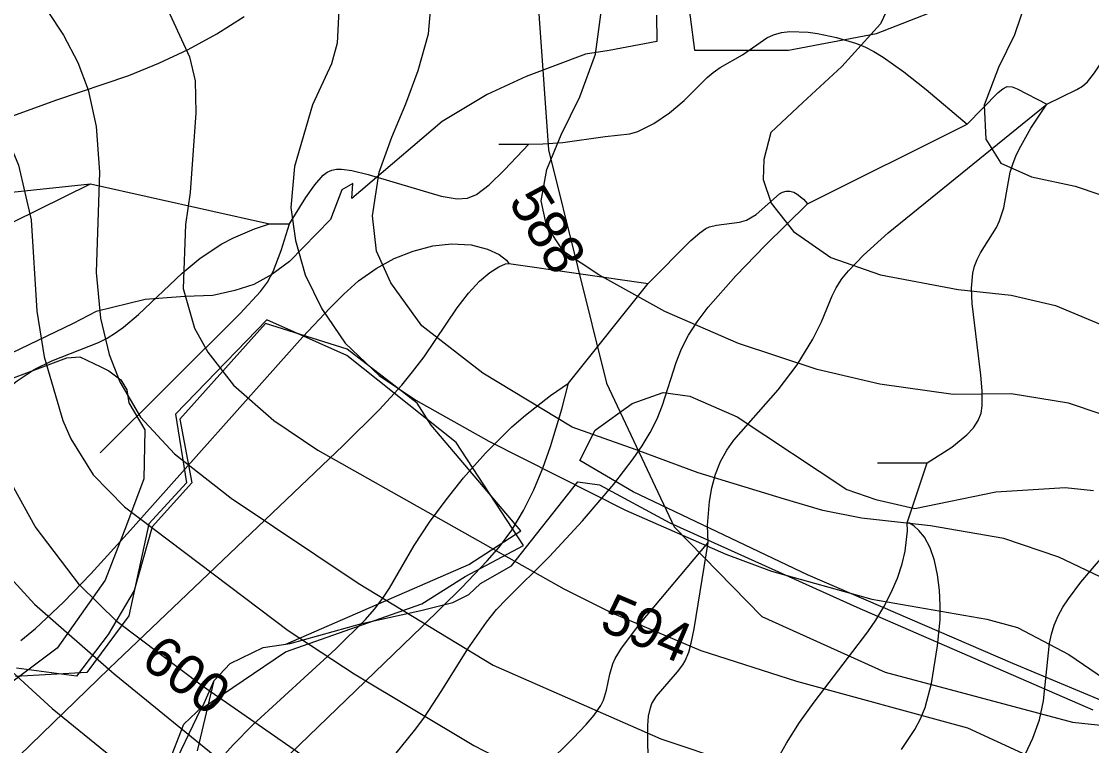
# Model space of a CAD drawing. Extents: x -709584 to -702006, y -1161789 to -1157496.
# Drawn here: x -706204.3 to -705935.7, y -1159597.9 to -1159416.2 of the extents above; entities that cross this region are included whole.
import ezdxf

# ---------------------------------------------------------------- set-up
doc = ezdxf.new("R2010")
doc.units = 0
for name, color, linetype in [('102_obvod PÚ', 7, 'Continuous'), ('120_vrstevnice hlavní', 7, 'Continuous'), ('121_vrstevnice hlavní_popis', 7, 'Continuous'), ('122_vrstevnice základní', 7, 'Continuous'), ('408_BPEJ_linie', 7, 'Continuous'), ('411_akumulovaný odtok', 7, 'Continuous'), ('419_LPIS PB', 7, 'Continuous')]:
    doc.layers.add(name, color=color, linetype=linetype)

msp = doc.modelspace()

# ---------------------------------------------------------------- linework, layer by layer
at = {"layer": '102_obvod PÚ'}
for points in [[(-706037.57, -1159406.69), (-706035.36, -1159423.47), (-706011.83, -1159423.45), (-705989.7, -1159419.24), (-705943.39, -1159401.12)], [(-706181.69, -1159691.02), (-706187.36, -1159679.89), (-706183.63, -1159651.54), (-706174.83, -1159621.23), (-706159.25, -1159588.81), (-706137.99, -1159574.35), (-706103.78, -1159562.33), (-706092.93, -1159555.48), (-706078.27, -1159547.73), (-706095.18, -1159521.9), (-706122.65, -1159500.07), (-706142.7, -1159491.07), (-706165.58, -1159514.77), (-706162.9, -1159531.96), (-706172.29, -1159542.26), (-706177.32, -1159565.38), (-706187.84, -1159579.54), (-706205.79, -1159580.54)]]:
    msp.add_lwpolyline(points, dxfattribs=at)
at = {"layer": '120_vrstevnice hlavní'}
for points in [[(-705926.57, -1159558.89), (-705943.93, -1159550.62), (-705957.74, -1159545.94), (-705976.17, -1159542.78), (-705993.49, -1159540.84), (-706003.21, -1159538.91), (-706012.77, -1159536.13), (-706034.5, -1159529.46), (-706050.02, -1159523.75), (-706066.04, -1159518.03), (-706088.5, -1159504.45), (-706103.81, -1159492.59), (-706111.62, -1159481.79), (-706115.16, -1159473.91), (-706116.15, -1159465.02), (-706114.55, -1159454.1), (-706111.31, -1159445.31), (-706107.86, -1159436.95), (-706104.74, -1159428.6), (-706102.13, -1159419.39), (-706101.41, -1159410.68)], [(-705977.91, -1159672.33), (-705989.06, -1159660.26), (-706004.08, -1159649.39), (-706019.52, -1159641.67), (-706040.12, -1159634.8), (-706092.5, -1159622.27), (-706100.47, -1159619.21), (-706133.93, -1159600.34), (-706158.82, -1159583.03), (-706180.27, -1159566.87), (-706189.71, -1159557.58), (-706200.86, -1159542.99), (-706206.16, -1159533.27), (-706213.45, -1159513.82), (-706215.59, -1159504.09), (-706219.03, -1159474.92), (-706221.74, -1159460.33), (-706226.89, -1159445.74), (-706238.05, -1159421.43), (-706240.91, -1159411.7)]]:
    msp.add_lwpolyline(points, dxfattribs=at)
at = {"layer": '122_vrstevnice základní'}
for points in [[(-705954.31, -1159568.3), (-705941.44, -1159575.03), (-705918.27, -1159590.9), (-705910.55, -1159595.05), (-705905.4, -1159596.62), (-705895.1, -1159597.34), (-705889.38, -1159595.91), (-705883.66, -1159593.62), (-705876.08, -1159588.9), (-705866.93, -1159581.03), (-705854.63, -1159567.16), (-705826.17, -1159528.98), (-705814.87, -1159511.81), (-705807.15, -1159497.51), (-705799.14, -1159480.35), (-705793.13, -1159463.19), (-705787.84, -1159443.17), (-705780.41, -1159400.26)], [(-706268.51, -1159404.27), (-706266.51, -1159427.15), (-706263.65, -1159440.88), (-706259.07, -1159452.32), (-706251.49, -1159475.2), (-706247.63, -1159491.22), (-706243.34, -1159514.1), (-706239.62, -1159527.83), (-706228.04, -1159553), (-706223.18, -1159560.44), (-706215.45, -1159570.16), (-706207.59, -1159578.46), (-706196.58, -1159588.61), (-706173.83, -1159607.06), (-706146.81, -1159626.23), (-706132.79, -1159633.95), (-706112.77, -1159642.67), (-706092.75, -1159649.39), (-706078.73, -1159653.11), (-706056.94, -1159662.66)], [(-706227.61, -1159404.27), (-706221.03, -1159420.28), (-706207.87, -1159445.46), (-706205.01, -1159452.32), (-706201.87, -1159466.05), (-706200.44, -1159488.93), (-706198.58, -1159500.37), (-706193.86, -1159516.39), (-706191.85, -1159520.97), (-706186.28, -1159529.98), (-706178.41, -1159537.99), (-706137.37, -1159569.02), (-706120.78, -1159579.89), (-706090.75, -1159597.91), (-706080.73, -1159603.06), (-706058.71, -1159611.78), (-706008.66, -1159627.23), (-705996.64, -1159632.52), (-705980.62, -1159642.24), (-705963.32, -1159656.69), (-705947.18, -1159676.09)], [(-705982.87, -1159404.41), (-705988.75, -1159416.86), (-705998.38, -1159427.58), (-706008.17, -1159436.6), (-706016.22, -1159444.08), (-706017.96, -1159450.91), (-706018.16, -1159455.87), (-706016.14, -1159461.87), (-706010.53, -1159468.91), (-706001.16, -1159475.45), (-705988.7, -1159479.78), (-705969.22, -1159483.47), (-705955.89, -1159484.91), (-705944.79, -1159487.53), (-705930.96, -1159493.24), (-705916.26, -1159498.78), (-705908.05, -1159498.65), (-705901.2, -1159496.29), (-705895.2, -1159491.71), (-705888.1, -1159485.02), (-705882.25, -1159477.53), (-705877.07, -1159467.98), (-705872.73, -1159453.47), (-705868.54, -1159437.24)], [(-706201.58, -1159407.7), (-706193.71, -1159419.71), (-706190.14, -1159426.58), (-706187.57, -1159433.44), (-706185.56, -1159442.59), (-706184.7, -1159454.04), (-706185.56, -1159479.21), (-706184.42, -1159490.65), (-706182.27, -1159499.8), (-706179.56, -1159506.67), (-706174.41, -1159515.53), (-706165.83, -1159524.69), (-706151.67, -1159535.84), (-706119.78, -1159557.15), (-706085.88, -1159577.74), (-706043.84, -1159596.19), (-706025.82, -1159602.2), (-706005.8, -1159605.63), (-705995.78, -1159608.35)], [(-705952, -1159410.39), (-705955.12, -1159419.61), (-705959.1, -1159427.8), (-705962.71, -1159437.24), (-705962.24, -1159445.8), (-705958.51, -1159451.8), (-705950.83, -1159455.27), (-705939.89, -1159457.54), (-705927.25, -1159461.88), (-705918.88, -1159464.66), (-705911.7, -1159465.72), (-705905.53, -1159464.22), (-705899.35, -1159459.8), (-705893.5, -1159452.47), (-705889.52, -1159443.59), (-705887.93, -1159434.02), (-705885.97, -1159418.12), (-705884.87, -1159409)], [(-706254.64, -1159411.13), (-706249.92, -1159431.73), (-706240.77, -1159452.32), (-706235.76, -1159466.05), (-706231.33, -1159486.64), (-706227.9, -1159514.1), (-706226.18, -1159520.97), (-706220.6, -1159534.7), (-706211.59, -1159550.86), (-706201.01, -1159562.44), (-706180.99, -1159579.89), (-706154.82, -1159601.2), (-706135.37, -1159614.93), (-706109.62, -1159630.37), (-706099.33, -1159635.66), (-706092.46, -1159638.09), (-706080.45, -1159640.81), (-706068.43, -1159642.24), (-706046.12, -1159648.96), (-706039.26, -1159651.82), (-706028.96, -1159657.69), (-706016.88, -1159667.56)], [(-706168.54, -1159411.13), (-706162.11, -1159425.15), (-706160.68, -1159431.15), (-706160.54, -1159439.16), (-706161.96, -1159459.19), (-706163.11, -1159467.19), (-706163.68, -1159483.21), (-706160.82, -1159493.22), (-706157.53, -1159499.23), (-706151.1, -1159507.52), (-706140.94, -1159516.39), (-706129.93, -1159523.83), (-706068.15, -1159558.58), (-706056.14, -1159564.59), (-706033.83, -1159574.03), (-706009.8, -1159581.75), (-705966.9, -1159593.48), (-705944.58, -1159603.77), (-705934.29, -1159610.64), (-705907.69, -1159631.37)], [(-706124.64, -1159413.42), (-706125.07, -1159421.72), (-706126.5, -1159426.86), (-706131.22, -1159437.16), (-706135.79, -1159452.61), (-706136.65, -1159462.9), (-706135.51, -1159471.2), (-706133.08, -1159479.78), (-706128.93, -1159488.36), (-706123.07, -1159496.94), (-706114.48, -1159505.09), (-706105.33, -1159511.24), (-706087.03, -1159521.54), (-706052.7, -1159538.84), (-706027.53, -1159549.86), (-706016.09, -1159554.15), (-705990.92, -1159561.15), (-705962.03, -1159566.16), (-705954.31, -1159568.3)], [(-705925.14, -1159517.52), (-705941.52, -1159511.97), (-705955.94, -1159509.7), (-705970.46, -1159509.8), (-705988.88, -1159507.27), (-706004.59, -1159503.6), (-706024.38, -1159497.01), (-706042.8, -1159489.05), (-706059.4, -1159479.79), (-706068.26, -1159473.94), (-706072.5, -1159467.42), (-706073.84, -1159461.26), (-706072.43, -1159453.41), (-706068.8, -1159444.71), (-706064.14, -1159435.16), (-706060.25, -1159424.49), (-706058.66, -1159412.7)]]:
    msp.add_lwpolyline(points, dxfattribs=at)
at = {"layer": '408_BPEJ_linie'}
for points in [[(-706111, -1159181.5), (-706096, -1159213), (-706094.5, -1159219), (-706079, -1159351), (-706075.5, -1159399), (-706072, -1159448.5), (-706057.5, -1159507), (-706040.5, -1159543), (-706018.5, -1159565.5), (-705987.5, -1159579.5), (-705940.5, -1159592), (-705917, -1159594.5), (-705903, -1159596), (-705878, -1159603), (-705866, -1159612), (-705861.5, -1159617.5), (-705858.5, -1159622.5)], [(-706216.5, -1159639.5), (-706203.5, -1159642.5), (-706185.5, -1159654), (-706184.5, -1159646.5), (-706163.5, -1159592.5), (-706158.73, -1159588), (-706155.88, -1159581.61), (-706151.87, -1159577.34), (-706143.61, -1159573.33), (-706137.91, -1159572.48), (-706092, -1159552.5), (-706079, -1159544), (-706101.5, -1159517.5), (-706105, -1159512), (-706122.5, -1159498.5), (-706143, -1159492), (-706164.5, -1159516), (-706161.5, -1159532), (-706171.5, -1159543), (-706176, -1159559), (-706182.5, -1159570), (-706190.5, -1159580.5), (-706205.5, -1159578.5)]]:
    msp.add_lwpolyline(points, dxfattribs=at)
at = {"layer": '411_akumulovaný odtok'}
for p, q in [((-706006.99, -1159462), (-705966.99, -1159442)), ((-706084.49, -1159447), (-706076.99, -1159447)), ((-706186.99, -1159457), (-706141.99, -1159467)), ((-706141.99, -1159467), (-706136.99, -1159467)), ((-706081.99, -1159477), (-706046.99, -1159482)), ((-706066.99, -1159507), (-706046.99, -1159482)), ((-705989.49, -1159527), (-705976.99, -1159527)), ((-705981.99, -1159542), (-705976.99, -1159527))]:
    msp.add_line(p, q, dxfattribs=at)
for points in [[(-706221.91, -1159445.56), (-706195.67, -1159435.99), (-706177.36, -1159429.81), (-706169.83, -1159426.74), (-706162.45, -1159423.26), (-706155.28, -1159419.36), (-706148.36, -1159415.02)], [(-706076.99, -1159447), (-706073.44, -1159446.97), (-706068.46, -1159446.66), (-706057.79, -1159445.08), (-706051.6, -1159444.46), (-706049.6, -1159443.86), (-706045.58, -1159441.88), (-706041.66, -1159439.22), (-706038, -1159436.1), (-706032.23, -1159430.28), (-706030.72, -1159429.03), (-706028.91, -1159427.84), (-706023.33, -1159424.67), (-706017.22, -1159420.39), (-706015.59, -1159419.61), (-706013.58, -1159419.06), (-706011.44, -1159418.81), (-706006.88, -1159418.96), (-706004.51, -1159419.27), (-705999.72, -1159420.25), (-705994.98, -1159421.7), (-705992.68, -1159422.65), (-705990.35, -1159423.83), (-705988.07, -1159425.19), (-705982.88, -1159428.9), (-705977.29, -1159433.35), (-705966.99, -1159442)], [(-705946.99, -1159437), (-705939.45, -1159433.29), (-705938.03, -1159432.45), (-705936.77, -1159431.4), (-705935.02, -1159429.13), (-705926.99, -1159417)], [(-705966.99, -1159442), (-705959.14, -1159434.06), (-705958.05, -1159433.12), (-705956.9, -1159432.56), (-705955.68, -1159432.69), (-705954.4, -1159433.2), (-705946.99, -1159437)], [(-706031.99, -1159547), (-706032.09, -1159542.71), (-706031.65, -1159536.66), (-706031.07, -1159533.26), (-706030.15, -1159529.85), (-706028.84, -1159526.66), (-706027.24, -1159523.76), (-706025.49, -1159521.25), (-706014.36, -1159508.7), (-706009.61, -1159502.41), (-706005.69, -1159495.99), (-706003.51, -1159491.57), (-706000.85, -1159485.1), (-705999.82, -1159483.06), (-705998.39, -1159480.86), (-705996.75, -1159478.78), (-705993, -1159474.86), (-705986.76, -1159469.29), (-705946.99, -1159437)], [(-705976.99, -1159527), (-705970.81, -1159523.05), (-705967.02, -1159519.93), (-705965.41, -1159518.18), (-705964.19, -1159516.36), (-705963.47, -1159514.5), (-705963.2, -1159512.69), (-705963.19, -1159508.92), (-705963.53, -1159505.01), (-705965.71, -1159487.04), (-705965.86, -1159483.15), (-705965.57, -1159479.43), (-705965.14, -1159477.66), (-705964.47, -1159475.97), (-705963.61, -1159474.34), (-705959.63, -1159467.96), (-705958.81, -1159466.29), (-705957.76, -1159462.97), (-705956.14, -1159454.1), (-705955.54, -1159452.09), (-705954.63, -1159449.82), (-705953.51, -1159447.5), (-705951, -1159443.06), (-705946.99, -1159437)], [(-706136.99, -1159467), (-706132.92, -1159460.41), (-706130.69, -1159457.2), (-706128.54, -1159454.81), (-706127.52, -1159454.07), (-706126.42, -1159453.56), (-706125.25, -1159453.33), (-706124, -1159453.31), (-706121.37, -1159453.66), (-706117.24, -1159454.68), (-706098.98, -1159460.06), (-706094.9, -1159460.76), (-706092.35, -1159460.62), (-706090.07, -1159459.67), (-706086.87, -1159457.25), (-706083.07, -1159453.48), (-706076.99, -1159447)], [(-706301.99, -1159477), (-706268.57, -1159477.26), (-706261.51, -1159477.04), (-706256.91, -1159476.55), (-706252.5, -1159475.49), (-706250.5, -1159474.67), (-706246.65, -1159472.59), (-706237.31, -1159466.46), (-706233.47, -1159464.24), (-706231.48, -1159463.31), (-706227.09, -1159461.9), (-706222.52, -1159460.95), (-706215.49, -1159459.96), (-706186.99, -1159457)], [(-706279.49, -1159492), (-706255.08, -1159492.31), (-706247.02, -1159492.22), (-706241.2, -1159491.62), (-706239.36, -1159491.19), (-706237.59, -1159490.57), (-706235.93, -1159489.72), (-706232.8, -1159487.53), (-706229.84, -1159484.94), (-706219.66, -1159475.19), (-706214.97, -1159471.52), (-706211.65, -1159469.46), (-706206.47, -1159466.64), (-706186.99, -1159457)], [(-706046.99, -1159482), (-706036.31, -1159471.19), (-706034.08, -1159469.26), (-706032.5, -1159468.2), (-706031.65, -1159467.8), (-706029.85, -1159467.32), (-706024.12, -1159466.64), (-706022.32, -1159466.14), (-706019.89, -1159464.67), (-706014.07, -1159459.5), (-706013.26, -1159459.06), (-706012.37, -1159458.81), (-706011.43, -1159458.82), (-706010.49, -1159459.12), (-706009.58, -1159459.62), (-706008.04, -1159460.87), (-706006.99, -1159462)], [(-706120.12, -1159612.04), (-706105.61, -1159594.14), (-706103.29, -1159591.04), (-706098.75, -1159584.13), (-706092.24, -1159573.62), (-706087.6, -1159566.93), (-706085.04, -1159563.81), (-706082.59, -1159561.2), (-706071.76, -1159550.46), (-706063.51, -1159541.54), (-706055.62, -1159532.32), (-706050.75, -1159525.98), (-706048.53, -1159522.74), (-706046.51, -1159519.41), (-706044.78, -1159515.98), (-706043.4, -1159512.5), (-706039.99, -1159501.84), (-706038.63, -1159498.39), (-706036.88, -1159494.98), (-706034.73, -1159491.61), (-706031.94, -1159487.93), (-706025.04, -1159480.06), (-706017.68, -1159472.44), (-706006.99, -1159462)], [(-706256.99, -1159522), (-706238.05, -1159519.94), (-706229.41, -1159518.74), (-706224.59, -1159517.76), (-706222.25, -1159517.13), (-706219.97, -1159516.35), (-706217.79, -1159515.39), (-706215.6, -1159514.15), (-706213.51, -1159512.72), (-706205.38, -1159506.41), (-706201.12, -1159503.57), (-706196.62, -1159501.43), (-706184.96, -1159496.81), (-706182.75, -1159495.67), (-706180.68, -1159494.38), (-706178.7, -1159492.95), (-706174.89, -1159489.79), (-706163.95, -1159479.42), (-706159.39, -1159475.65), (-706153.96, -1159472.07), (-706151.03, -1159470.53), (-706145.78, -1159468.26), (-706141.99, -1159467)], [(-706184.49, -1159524.5), (-706149.37, -1159489.48), (-706144.28, -1159484.03), (-706142.53, -1159481.67), (-706141.1, -1159478.94), (-706139.11, -1159473.72), (-706136.99, -1159467)], [(-706204.46, -1159571.58), (-706200.77, -1159568.57), (-706193.72, -1159561.95), (-706186.9, -1159554.86), (-706176.87, -1159543.85), (-706133.66, -1159495.4), (-706126.86, -1159488.17), (-706123.38, -1159484.69), (-706119.67, -1159481.33), (-706115.25, -1159478.2), (-706110.74, -1159475.76), (-706105.95, -1159473.85), (-706101.08, -1159472.57), (-706096.32, -1159472.03), (-706091.45, -1159472.31), (-706087.32, -1159473.35), (-706084.37, -1159474.74), (-706082.54, -1159476.1), (-706081.99, -1159477)], [(-706231.99, -1159622), (-706230.43, -1159620.61), (-706228.59, -1159619.25), (-706217.39, -1159611.71), (-706213.9, -1159608.93), (-706210.5, -1159605.9), (-706182.28, -1159578.53), (-706123.51, -1159522.63), (-706114.49, -1159513.66), (-706108.82, -1159507.5), (-706106.11, -1159504.19), (-706103.25, -1159500.37), (-706094.93, -1159488.07), (-706092.12, -1159484.43), (-706089.31, -1159481.42), (-706086.72, -1159479.26), (-706084.47, -1159477.82), (-706082.81, -1159477.06), (-706081.99, -1159477)], [(-706221.99, -1159682), (-706103.82, -1159568.14), (-706093.82, -1159558.3), (-706087.41, -1159551.59), (-706084.35, -1159548.07), (-706081.25, -1159543.86), (-706078.28, -1159538.96), (-706075.7, -1159533.72), (-706073.46, -1159528.28), (-706071.53, -1159522.92), (-706068.68, -1159513.54), (-706066.99, -1159507)], [(-706194.49, -1159629.5), (-706183.87, -1159623.96), (-706176.36, -1159619.76), (-706169.01, -1159615.18), (-706165.83, -1159612.9), (-706163.18, -1159610.71), (-706158.27, -1159605.67), (-706151.18, -1159597.71), (-706146.24, -1159592.71), (-706125.35, -1159573.67), (-706117.93, -1159566.28), (-706115.66, -1159563.67), (-706113.57, -1159560.95), (-706111.88, -1159558.4), (-706105.73, -1159547.71), (-706101.9, -1159541.87), (-706097.72, -1159536.22), (-706093.31, -1159530.7), (-706087.81, -1159524.52), (-706081.19, -1159517.98), (-706077.8, -1159514.98), (-706071.55, -1159510.08), (-706066.99, -1159507)], [(-705961.99, -1159644.5), (-705959.61, -1159625.67), (-705958.69, -1159619.56), (-705957.74, -1159614.57), (-705956.52, -1159609.78), (-705955.73, -1159607.45), (-705954.78, -1159605.13), (-705950.51, -1159596.07), (-705948.79, -1159591.43), (-705947.84, -1159586.72), (-705946.31, -1159572.24), (-705945.83, -1159569.92), (-705945.15, -1159567.68), (-705944.16, -1159565.39), (-705942.94, -1159563.2), (-705941.55, -1159561.06), (-705938.43, -1159556.92), (-705931.56, -1159548.88), (-705911.99, -1159527)], [(-706059.49, -1159674.5), (-706039.03, -1159651.15), (-706033.37, -1159643.93), (-706030.1, -1159638.96), (-706027.76, -1159634.26), (-706025.09, -1159627.82), (-706020.25, -1159618.49), (-706019.19, -1159616.09), (-706018.27, -1159613.47), (-706015.94, -1159605.35), (-706015, -1159602.69), (-706013.77, -1159599.95), (-706012.33, -1159597.28), (-706009.03, -1159592.08), (-706005.38, -1159587), (-705991.9, -1159569.39), (-705989.9, -1159566.43), (-705987.9, -1159563.09), (-705986.05, -1159559.53), (-705984.46, -1159555.89), (-705983.25, -1159552.3), (-705982.5, -1159549.11), (-705981.9, -1159544.06), (-705981.99, -1159542)], [(-705983.43, -1159598.92), (-705980.06, -1159593.87), (-705978.68, -1159591.21), (-705977.54, -1159588.34), (-705975.91, -1159582.3), (-705974.4, -1159572.86), (-705973.76, -1159566.38), (-705973.7, -1159562.73), (-705973.9, -1159558.9), (-705974.37, -1159555.08), (-705975.15, -1159551.47), (-705976.25, -1159548.26), (-705977.66, -1159545.63), (-705979.05, -1159543.92), (-705980.37, -1159542.75), (-705981.42, -1159542.1), (-705981.99, -1159542)], [(-706079.49, -1159609.5), (-706065.83, -1159596.07), (-706062.57, -1159592.65), (-706060.58, -1159590.3), (-706058.89, -1159587.82), (-706058.24, -1159586.5), (-706057.44, -1159583.97), (-706056.59, -1159580.01), (-706055.84, -1159577.43), (-706055.25, -1159576.08), (-706053.74, -1159573.5), (-706049.09, -1159567.37), (-706031.99, -1159547)], [(-706046.99, -1159604.5), (-706047.11, -1159592.83), (-706046.91, -1159590.54), (-706046.46, -1159588.4), (-706046.08, -1159587.39), (-706044.95, -1159585.5), (-706039.65, -1159579.43), (-706038.29, -1159577.61), (-706037.71, -1159576.64), (-706036.82, -1159574.49), (-706036.2, -1159572.2), (-706035.49, -1159568.66), (-706031.99, -1159547)]]:
    msp.add_lwpolyline(points, dxfattribs=at)
at = {"layer": '419_LPIS PB'}
for points in [[(-706044.95, -1159414.72), (-706044.82, -1159421.32), (-706056.81, -1159423.56), (-706062.75, -1159424.46), (-706077.66, -1159430.03), (-706087.42, -1159434.55), (-706098.68, -1159441.32), (-706121.4, -1159460.64), (-706121.16, -1159456.87), (-706123.87, -1159458.53), (-706126.69, -1159465.93), (-706136.98, -1159476.45), (-706141.48, -1159479.71), (-706145.99, -1159482.22), (-706150.75, -1159483.73), (-706156.25, -1159484.98), (-706163.26, -1159485.23), (-706173.27, -1159485.99), (-706185.54, -1159489), (-706191.3, -1159492.01), (-706209.07, -1159500.54)], [(-706224.43, -1159512.42), (-706192.89, -1159500.63), (-706189.64, -1159500.38), (-706184.38, -1159502.89), (-706182.38, -1159503.89), (-706179.37, -1159506.15), (-706177.87, -1159508.66), (-706177.37, -1159511.92), (-706173.3, -1159518.7), (-706173.6, -1159531), (-706177.9, -1159542.6), (-706183.3, -1159556.4), (-706195.3, -1159573.5), (-706218.4, -1159590.7)], [(-705910.7, -1159596.03), (-705955.5, -1159577.33), (-706007, -1159555.1), (-706050.75, -1159534.29), (-706064.14, -1159526.39), (-706060.27, -1159518.77), (-706051, -1159512.1), (-706043.22, -1159509.33), (-706036.59, -1159510.29), (-706024.65, -1159515.47), (-705997.18, -1159533.68), (-705989.92, -1159536.19), (-705980.06, -1159538.46), (-705959.73, -1159534.29), (-705942.37, -1159533.18), (-705935.24, -1159533.88)], [(-706160.11, -1159599.2), (-706155.88, -1159581.61), (-706151.87, -1159577.34), (-706143.61, -1159573.33), (-706136.85, -1159572.32), (-706118.83, -1159567.3), (-706104.06, -1159564.04), (-706096.05, -1159562.04), (-706092.05, -1159560.03), (-706089.05, -1159557.27), (-706081.3, -1159552.8), (-706064.68, -1159531.74), (-706059.22, -1159532.53), (-706041.58, -1159542.05), (-705994.66, -1159563.22), (-705935.39, -1159588.97)]]:
    msp.add_lwpolyline(points, dxfattribs=at)

# ---------------------------------------------------------------- texts
at = {"layer": '121_vrstevnice hlavní_popis'}
for s, rotation, p in [('588', 301.3468, (-706082.25, -1159461.42)), ('594', 336.9972, (-706059.59, -1159568.66)), ('600', 323.5329, (-706174.76, -1159577.49))]:
    msp.add_text(s, height=10, rotation=rotation, dxfattribs=at).set_placement(p)

doc.saveas('drawing.dxf')
